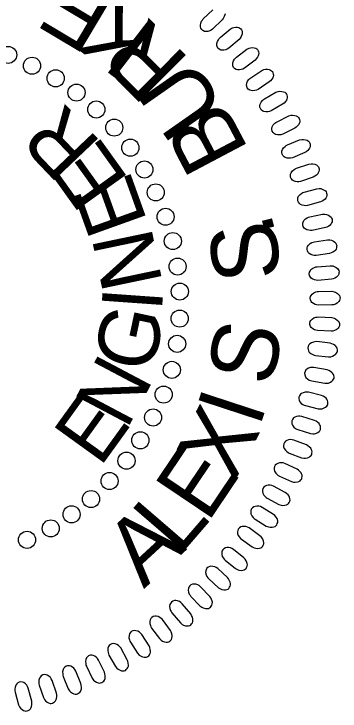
# Model space of a CAD drawing. Extents: x 477288 to 478604, y 497629 to 499448.
# Drawn here: x 477429.2 to 477459.8, y 499208.8 to 499274.1 of the extents above; entities that cross this region are included whole.
import ezdxf

# ---------------------------------------------------------------- set-up
doc = ezdxf.new("R2010")
doc.units = 0
doc.layers.add('Sheet PE Seal Cell', color=7, linetype='Continuous')

msp = doc.modelspace()

# ---------------------------------------------------------------- linework, layer by layer
at = {"layer": 'Sheet PE Seal Cell'}
msp.add_lwpolyline([(477449.002, 499274.089), (477448.987, 499273.991), (477448.925, 499273.838), (477448.838, 499273.671), (477448.739, 499273.544), (477447.839, 499272.667), (477447.7, 499272.566), (477447.568, 499272.502), (477447.392, 499272.456), (477447.213, 499272.439), (477447.088, 499272.454), (477446.936, 499272.526), (477446.818, 499272.62), (477446.743, 499272.756), (477446.707, 499272.865), (477446.69, 499273.026), (477446.729, 499273.229), (477446.812, 499273.403), (477446.885, 499273.514), (477446.968, 499273.615), (477447.852, 499274.465)], dxfattribs=at)
for points in [[(477448.552, 499271.872), (477449.487, 499272.666), (477449.679, 499272.779), (477449.819, 499272.83), (477450.021, 499272.854), (477450.168, 499272.851), (477450.301, 499272.817), (477450.399, 499272.764), (477450.487, 499272.69), (477450.544, 499272.592), (477450.599, 499272.481), (477450.621, 499272.363), (477450.612, 499272.219), (477450.59, 499272.121), (477450.52, 499271.973), (477450.421, 499271.811), (477450.315, 499271.691), (477449.361, 499270.873), (477449.217, 499270.78), (477449.082, 499270.724), (477448.902, 499270.689), (477448.723, 499270.684), (477448.599, 499270.707), (477448.452, 499270.788), (477448.34, 499270.89), (477448.273, 499271.029), (477448.244, 499271.141), (477448.237, 499271.302), (477448.29, 499271.503), (477448.383, 499271.671), (477448.463, 499271.777)], [(477450.074, 499270.046), (477451.058, 499270.779), (477451.256, 499270.88), (477451.399, 499270.922), (477451.602, 499270.934), (477451.748, 499270.921), (477451.879, 499270.879), (477451.974, 499270.819), (477452.057, 499270.74), (477452.107, 499270.639), (477452.155, 499270.525), (477452.17, 499270.406), (477452.152, 499270.262), (477452.124, 499270.166), (477452.044, 499270.023), (477451.936, 499269.868), (477451.822, 499269.754), (477450.819, 499268.998), (477450.669, 499268.914), (477450.53, 499268.867), (477450.349, 499268.843), (477450.17, 499268.849), (477450.048, 499268.88), (477449.906, 499268.97), (477449.8, 499269.078), (477449.744, 499269.221), (477449.721, 499269.336), (477449.724, 499269.497), (477449.789, 499269.694), (477449.893, 499269.856), (477449.979, 499269.956)], [(477451.417, 499268.111), (477452.445, 499268.781), (477452.649, 499268.869), (477452.794, 499268.902), (477452.998, 499268.901), (477453.143, 499268.879), (477453.271, 499268.828), (477453.361, 499268.763), (477453.44, 499268.679), (477453.483, 499268.575), (477453.524, 499268.458), (477453.532, 499268.338), (477453.504, 499268.196), (477453.471, 499268.102), (477453.382, 499267.964), (477453.264, 499267.816), (477453.143, 499267.71), (477452.094, 499267.018), (477451.94, 499266.944), (477451.798, 499266.905), (477451.616, 499266.893), (477451.438, 499266.911), (477451.318, 499266.949), (477451.182, 499267.047), (477451.083, 499267.162), (477451.036, 499267.309), (477451.02, 499267.424), (477451.034, 499267.584), (477451.111, 499267.777), (477451.225, 499267.932), (477451.317, 499268.028)], [(477452.708, 499266.142), (477453.776, 499266.746), (477453.985, 499266.821), (477454.132, 499266.845), (477454.335, 499266.831), (477454.478, 499266.8), (477454.603, 499266.742), (477454.689, 499266.671), (477454.762, 499266.583), (477454.799, 499266.475), (477454.832, 499266.357), (477454.832, 499266.236), (477454.797, 499266.096), (477454.757, 499266.004), (477454.66, 499265.872), (477454.533, 499265.732), (477454.405, 499265.634), (477453.315, 499265.009), (477453.156, 499264.945), (477453.013, 499264.915), (477452.83, 499264.914), (477452.653, 499264.943), (477452.536, 499264.989), (477452.406, 499265.095), (477452.315, 499265.216), (477452.276, 499265.365), (477452.269, 499265.482), (477452.293, 499265.641), (477452.381, 499265.828), (477452.504, 499265.976), (477452.602, 499266.065)], [(477453.875, 499263.99), (477454.978, 499264.526), (477455.191, 499264.588), (477455.34, 499264.602), (477455.542, 499264.576), (477455.683, 499264.536), (477455.804, 499264.47), (477455.885, 499264.393), (477455.952, 499264.3), (477455.983, 499264.191), (477456.008, 499264.071), (477456, 499263.951), (477455.956, 499263.813), (477455.911, 499263.724), (477455.805, 499263.598), (477455.67, 499263.466), (477455.536, 499263.376), (477454.409, 499262.82), (477454.247, 499262.767), (477454.102, 499262.746), (477453.92, 499262.757), (477453.745, 499262.797), (477453.63, 499262.85), (477453.508, 499262.965), (477453.425, 499263.09), (477453.396, 499263.242), (477453.395, 499263.358), (477453.428, 499263.516), (477453.529, 499263.697), (477453.661, 499263.837), (477453.764, 499263.92)], [(477454.855, 499261.812), (477455.991, 499262.278), (477456.207, 499262.327), (477456.357, 499262.332), (477456.556, 499262.292), (477456.695, 499262.244), (477456.811, 499262.17), (477456.888, 499262.089), (477456.948, 499261.992), (477456.972, 499261.882), (477456.99, 499261.759), (477456.975, 499261.64), (477456.922, 499261.505), (477456.871, 499261.42), (477456.758, 499261.3), (477456.615, 499261.177), (477456.475, 499261.096), (477455.316, 499260.612), (477455.15, 499260.568), (477455.005, 499260.557), (477454.822, 499260.579), (477454.651, 499260.63), (477454.54, 499260.69), (477454.425, 499260.812), (477454.35, 499260.943), (477454.331, 499261.096), (477454.337, 499261.212), (477454.38, 499261.368), (477454.492, 499261.542), (477454.633, 499261.673), (477454.741, 499261.75)], [(477455.703, 499259.623), (477456.866, 499260.016), (477457.085, 499260.051), (477457.234, 499260.047), (477457.431, 499259.995), (477457.566, 499259.937), (477457.678, 499259.857), (477457.749, 499259.771), (477457.803, 499259.67), (477457.82, 499259.558), (477457.83, 499259.436), (477457.808, 499259.317), (477457.746, 499259.186), (477457.69, 499259.104), (477457.57, 499258.992), (477457.419, 499258.878), (477457.275, 499258.805), (477456.087, 499258.395), (477455.92, 499258.362), (477455.773, 499258.36), (477455.593, 499258.394), (477455.425, 499258.455), (477455.318, 499258.522), (477455.211, 499258.651), (477455.145, 499258.787), (477455.135, 499258.941), (477455.148, 499259.056), (477455.201, 499259.208), (477455.324, 499259.376), (477455.473, 499259.498), (477455.585, 499259.567)], [(477456.429, 499257.386), (477457.614, 499257.706), (477457.835, 499257.727), (477457.983, 499257.714), (477458.177, 499257.649), (477458.308, 499257.584), (477458.414, 499257.496), (477458.479, 499257.406), (477458.528, 499257.302), (477458.538, 499257.189), (477458.541, 499257.066), (477458.51, 499256.95), (477458.441, 499256.822), (477458.379, 499256.744), (477458.252, 499256.639), (477458.095, 499256.535), (477457.947, 499256.472), (477456.735, 499256.137), (477456.566, 499256.115), (477456.419, 499256.122), (477456.242, 499256.167), (477456.078, 499256.238), (477455.975, 499256.312), (477455.877, 499256.448), (477455.819, 499256.587), (477455.819, 499256.742), (477455.84, 499256.856), (477455.902, 499257.004), (477456.035, 499257.163), (477456.191, 499257.276), (477456.308, 499257.338)], [(477456.947, 499255.07), (477458.15, 499255.314), (477458.372, 499255.322), (477458.519, 499255.299), (477458.708, 499255.222), (477458.835, 499255.15), (477458.935, 499255.055), (477458.995, 499254.961), (477459.037, 499254.855), (477459.039, 499254.741), (477459.034, 499254.618), (477458.996, 499254.503), (477458.919, 499254.381), (477458.853, 499254.306), (477458.72, 499254.211), (477458.556, 499254.116), (477458.404, 499254.063), (477457.174, 499253.804), (477457.004, 499253.792), (477456.858, 499253.809), (477456.684, 499253.865), (477456.524, 499253.947), (477456.427, 499254.026), (477456.337, 499254.168), (477456.288, 499254.311), (477456.297, 499254.465), (477456.325, 499254.577), (477456.397, 499254.722), (477456.54, 499254.873), (477456.702, 499254.975), (477456.823, 499255.03)], [(477457.394, 499252.743), (477458.61, 499252.911), (477458.832, 499252.904), (477458.978, 499252.872), (477459.161, 499252.784), (477459.283, 499252.703), (477459.378, 499252.602), (477459.432, 499252.505), (477459.466, 499252.396), (477459.462, 499252.283), (477459.449, 499252.16), (477459.405, 499252.048), (477459.32, 499251.93), (477459.249, 499251.86), (477459.11, 499251.773), (477458.941, 499251.689), (477458.786, 499251.645), (477457.542, 499251.465), (477457.371, 499251.464), (477457.227, 499251.489), (477457.056, 499251.556), (477456.903, 499251.647), (477456.81, 499251.733), (477456.729, 499251.88), (477456.689, 499252.026), (477456.708, 499252.179), (477456.743, 499252.29), (477456.823, 499252.43), (477456.975, 499252.571), (477457.144, 499252.663), (477457.269, 499252.709)], [(477457.648, 499250.402), (477458.871, 499250.494), (477459.092, 499250.473), (477459.236, 499250.432), (477459.414, 499250.332), (477459.531, 499250.244), (477459.618, 499250.138), (477459.666, 499250.037), (477459.694, 499249.925), (477459.682, 499249.813), (477459.662, 499249.692), (477459.61, 499249.583), (477459.518, 499249.471), (477459.443, 499249.405), (477459.299, 499249.327), (477459.125, 499249.253), (477458.967, 499249.219), (477457.715, 499249.117), (477457.544, 499249.127), (477457.401, 499249.162), (477457.236, 499249.239), (477457.088, 499249.34), (477457.001, 499249.431), (477456.93, 499249.583), (477456.899, 499249.731), (477456.927, 499249.883), (477456.969, 499249.991), (477457.059, 499250.125), (477457.219, 499250.257), (477457.393, 499250.338), (477457.52, 499250.377)], [(477457.772, 499248.079), (477458.998, 499248.094), (477459.218, 499248.06), (477459.359, 499248.009), (477459.53, 499247.899), (477459.64, 499247.803), (477459.722, 499247.692), (477459.763, 499247.588), (477459.784, 499247.476), (477459.765, 499247.364), (477459.737, 499247.244), (477459.679, 499247.138), (477459.58, 499247.033), (477459.501, 499246.972), (477459.352, 499246.903), (477459.173, 499246.841), (477459.014, 499246.816), (477457.758, 499246.793), (477457.588, 499246.814), (477457.448, 499246.857), (477457.287, 499246.945), (477457.146, 499247.055), (477457.065, 499247.151), (477457.003, 499247.307), (477456.982, 499247.457), (477457.02, 499247.607), (477457.068, 499247.712), (477457.166, 499247.841), (477457.334, 499247.961), (477457.513, 499248.031), (477457.643, 499248.063)], [(477457.775, 499245.691), (477459, 499245.629), (477459.217, 499245.581), (477459.354, 499245.521), (477459.518, 499245.401), (477459.622, 499245.298), (477459.696, 499245.182), (477459.731, 499245.076), (477459.745, 499244.962), (477459.72, 499244.852), (477459.684, 499244.734), (477459.619, 499244.632), (477459.514, 499244.533), (477459.431, 499244.477), (477459.278, 499244.417), (477459.096, 499244.367), (477458.935, 499244.352), (477457.68, 499244.409), (477457.512, 499244.44), (477457.375, 499244.492), (477457.22, 499244.589), (477457.086, 499244.708), (477457.011, 499244.809), (477456.96, 499244.968), (477456.947, 499245.12), (477456.995, 499245.266), (477457.05, 499245.369), (477457.155, 499245.491), (477457.331, 499245.601), (477457.514, 499245.66), (477457.644, 499245.682)], [(477457.48, 499242.094), (477458.699, 499241.955), (477458.92, 499241.968), (477459.066, 499242.003), (477459.247, 499242.096), (477459.367, 499242.18), (477459.459, 499242.283), (477459.511, 499242.382), (477459.543, 499242.491), (477459.535, 499242.604), (477459.519, 499242.727), (477459.472, 499242.837), (477459.385, 499242.953), (477459.313, 499243.021), (477459.171, 499243.105), (477458.999, 499243.185), (477458.843, 499243.225), (477457.596, 499243.375), (477457.425, 499243.371), (477457.281, 499243.342), (477457.112, 499243.271), (477456.961, 499243.176), (477456.871, 499243.088), (477456.793, 499242.939), (477456.757, 499242.793), (477456.78, 499242.639), (477456.818, 499242.53), (477456.902, 499242.392), (477457.057, 499242.255), (477457.228, 499242.167), (477457.353, 499242.124)], [(477457.135, 499239.691), (477458.343, 499239.476), (477458.566, 499239.474), (477458.712, 499239.501), (477458.899, 499239.581), (477459.024, 499239.658), (477459.122, 499239.755), (477459.179, 499239.85), (477459.219, 499239.957), (477459.219, 499240.071), (477459.21, 499240.194), (477459.17, 499240.308), (477459.089, 499240.428), (477459.022, 499240.501), (477458.886, 499240.594), (477458.72, 499240.684), (477458.567, 499240.734), (477457.331, 499240.962), (477457.16, 499240.969), (477457.015, 499240.949), (477456.842, 499240.889), (477456.685, 499240.804), (477456.589, 499240.721), (477456.503, 499240.578), (477456.457, 499240.434), (477456.47, 499240.279), (477456.502, 499240.168), (477456.577, 499240.025), (477456.723, 499239.878), (477456.888, 499239.78), (477457.01, 499239.728)], [(477456.546, 499237.379), (477457.738, 499237.088), (477457.96, 499237.072), (477458.108, 499237.09), (477458.3, 499237.159), (477458.429, 499237.227), (477458.533, 499237.318), (477458.597, 499237.41), (477458.643, 499237.514), (477458.65, 499237.627), (477458.649, 499237.751), (477458.616, 499237.867), (477458.543, 499237.992), (477458.48, 499238.069), (477458.351, 499238.17), (477458.191, 499238.27), (477458.041, 499238.33), (477456.822, 499238.635), (477456.652, 499238.653), (477456.506, 499238.642), (477456.329, 499238.593), (477456.167, 499238.518), (477456.066, 499238.442), (477455.971, 499238.304), (477455.916, 499238.162), (477455.92, 499238.008), (477455.944, 499237.895), (477456.01, 499237.748), (477456.147, 499237.591), (477456.306, 499237.483), (477456.424, 499237.424)], [(477455.841, 499235.132), (477457.012, 499234.768), (477457.232, 499234.739), (477457.381, 499234.747), (477457.577, 499234.803), (477457.711, 499234.863), (477457.82, 499234.947), (477457.889, 499235.034), (477457.941, 499235.136), (477457.955, 499235.249), (477457.963, 499235.372), (477457.937, 499235.49), (477457.872, 499235.62), (477457.814, 499235.701), (477457.691, 499235.809), (477457.538, 499235.92), (477457.392, 499235.989), (477456.195, 499236.369), (477456.025, 499236.398), (477455.879, 499236.396), (477455.7, 499236.359), (477455.533, 499236.293), (477455.428, 499236.224), (477455.325, 499236.092), (477455.261, 499235.954), (477455.255, 499235.801), (477455.271, 499235.685), (477455.328, 499235.535), (477455.455, 499235.371), (477455.607, 499235.252), (477455.721, 499235.186)], [(477455.029, 499232.94), (477456.175, 499232.503), (477456.393, 499232.46), (477456.542, 499232.458), (477456.741, 499232.503), (477456.878, 499232.554), (477456.992, 499232.631), (477457.067, 499232.714), (477457.126, 499232.812), (477457.147, 499232.923), (477457.162, 499233.046), (477457.144, 499233.165), (477457.087, 499233.298), (477457.034, 499233.382), (477456.918, 499233.499), (477456.772, 499233.619), (477456.631, 499233.697), (477455.459, 499234.152), (477455.293, 499234.191), (477455.146, 499234.199), (477454.966, 499234.172), (477454.795, 499234.118), (477454.686, 499234.055), (477454.574, 499233.93), (477454.502, 499233.797), (477454.486, 499233.644), (477454.495, 499233.528), (477454.543, 499233.373), (477454.659, 499233.202), (477454.803, 499233.074), (477454.913, 499233)], [(477454.103, 499230.774), (477455.22, 499230.266), (477455.435, 499230.208), (477455.583, 499230.198), (477455.784, 499230.229), (477455.924, 499230.273), (477456.043, 499230.342), (477456.123, 499230.42), (477456.187, 499230.514), (477456.216, 499230.624), (477456.239, 499230.746), (477456.227, 499230.866), (477456.18, 499231.002), (477456.132, 499231.09), (477456.024, 499231.213), (477455.886, 499231.342), (477455.749, 499231.429), (477454.609, 499231.956), (477454.445, 499232.006), (477454.3, 499232.023), (477454.117, 499232.008), (477453.944, 499231.964), (477453.831, 499231.908), (477453.711, 499231.79), (477453.631, 499231.662), (477453.606, 499231.509), (477453.608, 499231.394), (477453.645, 499231.237), (477453.75, 499231.058), (477453.886, 499230.922), (477453.991, 499230.841)], [(477452.965, 499228.695), (477454.048, 499228.118), (477454.259, 499228.048), (477454.407, 499228.028), (477454.609, 499228.047), (477454.752, 499228.081), (477454.875, 499228.143), (477454.959, 499228.216), (477455.03, 499228.306), (477455.065, 499228.414), (477455.095, 499228.534), (477455.092, 499228.654), (477455.052, 499228.793), (477455.011, 499228.884), (477454.91, 499229.013), (477454.78, 499229.15), (477454.65, 499229.246), (477453.545, 499229.844), (477453.385, 499229.904), (477453.24, 499229.93), (477453.058, 499229.926), (477452.881, 499229.894), (477452.765, 499229.845), (477452.638, 499229.735), (477452.55, 499229.612), (477452.515, 499229.461), (477452.51, 499229.345), (477452.538, 499229.187), (477452.632, 499229.002), (477452.758, 499228.857), (477452.859, 499228.77)], [(477451.824, 499226.739), (477452.868, 499226.094), (477453.074, 499226.011), (477453.22, 499225.981), (477453.423, 499225.988), (477453.568, 499226.013), (477453.695, 499226.066), (477453.784, 499226.134), (477453.86, 499226.22), (477453.901, 499226.325), (477453.938, 499226.443), (477453.943, 499226.563), (477453.912, 499226.705), (477453.877, 499226.798), (477453.785, 499226.933), (477453.663, 499227.079), (477453.539, 499227.182), (477452.474, 499227.848), (477452.318, 499227.918), (477452.175, 499227.953), (477451.993, 499227.961), (477451.815, 499227.939), (477451.695, 499227.898), (477451.563, 499227.796), (477451.467, 499227.679), (477451.423, 499227.531), (477451.41, 499227.415), (477451.428, 499227.255), (477451.51, 499227.065), (477451.627, 499226.912), (477451.721, 499226.819)], [(477450.541, 499224.854), (477451.542, 499224.145), (477451.743, 499224.049), (477451.887, 499224.011), (477452.09, 499224.004), (477452.237, 499224.02), (477452.366, 499224.066), (477452.458, 499224.128), (477452.54, 499224.208), (477452.588, 499224.311), (477452.633, 499224.426), (477452.645, 499224.546), (477452.623, 499224.689), (477452.593, 499224.783), (477452.51, 499224.926), (477452.398, 499225.078), (477452.281, 499225.189), (477451.259, 499225.92), (477451.108, 499226), (477450.968, 499226.044), (477450.786, 499226.063), (477450.608, 499226.052), (477450.487, 499226.019), (477450.347, 499225.926), (477450.244, 499225.815), (477450.19, 499225.67), (477450.171, 499225.555), (477450.178, 499225.394), (477450.248, 499225.199), (477450.356, 499225.04), (477450.444, 499224.941)], [(477449.019, 499222.89), (477449.974, 499222.12), (477450.167, 499222.011), (477450.309, 499221.964), (477450.512, 499221.944), (477450.658, 499221.952), (477450.791, 499221.989), (477450.888, 499222.045), (477450.973, 499222.12), (477451.028, 499222.22), (477451.08, 499222.332), (477451.099, 499222.45), (477451.087, 499222.595), (477451.063, 499222.691), (477450.989, 499222.838), (477450.886, 499222.997), (477450.777, 499223.115), (477449.803, 499223.909), (477449.657, 499223.999), (477449.52, 499224.051), (477449.34, 499224.082), (477449.161, 499224.082), (477449.038, 499224.056), (477448.892, 499223.972), (477448.783, 499223.868), (477448.72, 499223.727), (477448.693, 499223.613), (477448.691, 499223.452), (477448.748, 499223.253), (477448.846, 499223.087), (477448.928, 499222.983)], [(477447.474, 499221.15), (477448.378, 499220.321), (477448.565, 499220.201), (477448.703, 499220.145), (477448.904, 499220.113), (477449.05, 499220.11), (477449.185, 499220.139), (477449.285, 499220.189), (477449.376, 499220.259), (477449.436, 499220.355), (477449.495, 499220.464), (477449.522, 499220.581), (477449.519, 499220.725), (477449.501, 499220.823), (477449.436, 499220.975), (477449.344, 499221.139), (477449.242, 499221.264), (477448.32, 499222.119), (477448.18, 499222.216), (477448.046, 499222.277), (477447.868, 499222.319), (477447.689, 499222.331), (477447.565, 499222.313), (477447.415, 499222.238), (477447.299, 499222.141), (477447.228, 499222.004), (477447.194, 499221.893), (477447.181, 499221.732), (477447.225, 499221.529), (477447.312, 499221.358), (477447.388, 499221.249)], [(477445.803, 499219.501), (477446.655, 499218.617), (477446.833, 499218.485), (477446.968, 499218.42), (477447.166, 499218.376), (477447.312, 499218.364), (477447.448, 499218.385), (477447.551, 499218.428), (477447.647, 499218.492), (477447.713, 499218.584), (477447.778, 499218.688), (477447.813, 499218.804), (477447.818, 499218.948), (477447.806, 499219.048), (477447.751, 499219.202), (477447.67, 499219.373), (477447.576, 499219.503), (477446.709, 499220.413), (477446.575, 499220.52), (477446.446, 499220.59), (477446.271, 499220.643), (477446.094, 499220.665), (477445.968, 499220.656), (477445.813, 499220.59), (477445.692, 499220.5), (477445.612, 499220.368), (477445.571, 499220.26), (477445.548, 499220.099), (477445.58, 499219.895), (477445.656, 499219.718), (477445.724, 499219.604)], [(477444.023, 499217.965), (477444.817, 499217.029), (477444.987, 499216.885), (477445.117, 499216.813), (477445.313, 499216.756), (477445.457, 499216.735), (477445.595, 499216.747), (477445.7, 499216.784), (477445.799, 499216.842), (477445.871, 499216.93), (477445.943, 499217.03), (477445.984, 499217.143), (477446, 499217.287), (477445.994, 499217.386), (477445.948, 499217.544), (477445.877, 499217.719), (477445.792, 499217.855), (477444.985, 499218.819), (477444.858, 499218.933), (477444.732, 499219.011), (477444.562, 499219.074), (477444.386, 499219.109), (477444.26, 499219.106), (477444.101, 499219.05), (477443.975, 499218.969), (477443.886, 499218.842), (477443.839, 499218.736), (477443.806, 499218.578), (477443.825, 499218.371), (477443.89, 499218.19), (477443.951, 499218.073)], [(477442.128, 499216.533), (477442.861, 499215.549), (477443.022, 499215.396), (477443.147, 499215.315), (477443.338, 499215.246), (477443.483, 499215.216), (477443.62, 499215.22), (477443.727, 499215.25), (477443.829, 499215.301), (477443.907, 499215.384), (477443.985, 499215.48), (477444.033, 499215.59), (477444.057, 499215.733), (477444.058, 499215.832), (477444.022, 499215.992), (477443.963, 499216.172), (477443.886, 499216.314), (477443.141, 499217.326), (477443.021, 499217.448), (477442.901, 499217.533), (477442.735, 499217.607), (477442.562, 499217.652), (477442.436, 499217.658), (477442.274, 499217.612), (477442.142, 499217.538), (477442.046, 499217.417), (477441.992, 499217.315), (477441.95, 499217.159), (477441.956, 499216.952), (477442.009, 499216.767), (477442.062, 499216.646)], [(477440.144, 499215.2), (477440.814, 499214.172), (477440.965, 499214.009), (477441.085, 499213.92), (477441.272, 499213.84), (477441.413, 499213.8), (477441.551, 499213.795), (477441.66, 499213.819), (477441.765, 499213.863), (477441.848, 499213.941), (477441.932, 499214.032), (477441.987, 499214.139), (477442.019, 499214.28), (477442.027, 499214.379), (477442.001, 499214.541), (477441.953, 499214.724), (477441.885, 499214.87), (477441.205, 499215.927), (477441.093, 499216.057), (477440.98, 499216.149), (477440.818, 499216.233), (477440.647, 499216.29), (477440.522, 499216.303), (477440.358, 499216.268), (477440.221, 499216.203), (477440.118, 499216.088), (477440.058, 499215.988), (477440.005, 499215.836), (477439.999, 499215.629), (477440.04, 499215.441), (477440.086, 499215.316)], [(477438.129, 499214.011), (477438.733, 499212.943), (477438.874, 499212.77), (477438.988, 499212.674), (477439.169, 499212.582), (477439.308, 499212.535), (477439.445, 499212.521), (477439.555, 499212.537), (477439.663, 499212.575), (477439.75, 499212.647), (477439.84, 499212.733), (477439.902, 499212.836), (477439.943, 499212.975), (477439.956, 499213.073), (477439.941, 499213.237), (477439.904, 499213.422), (477439.846, 499213.572), (477439.234, 499214.67), (477439.13, 499214.807), (477439.022, 499214.906), (477438.866, 499215), (477438.7, 499215.067), (477438.576, 499215.088), (477438.409, 499215.063), (477438.269, 499215.007), (477438.16, 499214.899), (477438.093, 499214.803), (477438.031, 499214.654), (477438.011, 499214.448), (477438.04, 499214.258), (477438.079, 499214.131)], [(477436.018, 499212.951), (477436.554, 499211.848), (477436.683, 499211.667), (477436.791, 499211.563), (477436.966, 499211.46), (477437.102, 499211.404), (477437.237, 499211.381), (477437.349, 499211.391), (477437.458, 499211.422), (477437.55, 499211.489), (477437.645, 499211.568), (477437.713, 499211.667), (477437.763, 499211.803), (477437.783, 499211.901), (477437.778, 499212.065), (477437.753, 499212.253), (477437.704, 499212.406), (477437.161, 499213.54), (477437.067, 499213.682), (477436.965, 499213.788), (477436.815, 499213.892), (477436.654, 499213.969), (477436.531, 499213.999), (477436.364, 499213.983), (477436.22, 499213.936), (477436.104, 499213.835), (477436.031, 499213.745), (477435.961, 499213.6), (477435.927, 499213.395), (477435.945, 499213.204), (477435.975, 499213.074)], [(477433.846, 499211.989), (477434.311, 499210.853), (477434.43, 499210.665), (477434.53, 499210.555), (477434.699, 499210.441), (477434.83, 499210.376), (477434.965, 499210.345), (477435.076, 499210.348), (477435.188, 499210.372), (477435.283, 499210.433), (477435.383, 499210.506), (477435.457, 499210.601), (477435.516, 499210.734), (477435.541, 499210.83), (477435.547, 499210.994), (477435.534, 499211.183), (477435.494, 499211.339), (477435.024, 499212.504), (477434.939, 499212.653), (477434.844, 499212.764), (477434.701, 499212.878), (477434.544, 499212.965), (477434.425, 499213.002), (477434.256, 499212.998), (477434.11, 499212.959), (477433.987, 499212.866), (477433.909, 499212.779), (477433.829, 499212.639), (477433.783, 499212.437), (477433.789, 499212.245), (477433.811, 499212.114)], [(477431.593, 499211.191), (477431.987, 499210.029), (477432.092, 499209.833), (477432.186, 499209.718), (477432.348, 499209.593), (477432.475, 499209.52), (477432.606, 499209.481), (477432.718, 499209.476), (477432.831, 499209.493), (477432.93, 499209.548), (477433.034, 499209.615), (477433.114, 499209.705), (477433.181, 499209.833), (477433.212, 499209.928), (477433.228, 499210.092), (477433.227, 499210.281), (477433.198, 499210.439), (477432.801, 499211.631), (477432.726, 499211.785), (477432.638, 499211.903), (477432.503, 499212.025), (477432.351, 499212.122), (477432.234, 499212.166), (477432.066, 499212.172), (477431.918, 499212.143), (477431.789, 499212.057), (477431.706, 499211.977), (477431.618, 499211.841), (477431.559, 499211.643), (477431.553, 499211.45), (477431.566, 499211.319)], [(477429.336, 499210.54), (477429.655, 499209.356), (477429.749, 499209.154), (477429.835, 499209.032), (477429.988, 499208.898), (477430.111, 499208.817), (477430.24, 499208.77), (477430.351, 499208.759), (477430.465, 499208.768), (477430.567, 499208.817), (477430.675, 499208.877), (477430.761, 499208.962), (477430.836, 499209.086), (477430.873, 499209.179), (477430.899, 499209.34), (477430.91, 499209.529), (477430.89, 499209.689), (477430.57, 499210.904), (477430.504, 499211.062), (477430.424, 499211.185), (477430.296, 499211.316), (477430.152, 499211.421), (477430.037, 499211.473), (477429.87, 499211.49), (477429.72, 499211.47), (477429.586, 499211.393), (477429.498, 499211.317), (477429.401, 499211.188), (477429.33, 499210.993), (477429.312, 499210.802), (477429.317, 499210.669)]]:
    msp.add_lwpolyline(points, close=True, dxfattribs=at)
for centre in [(477428.685, 499270.25), (477430.918, 499269.233), (477433.133, 499268.054), (477435.088, 499266.717), (477436.94, 499265.129), (477438.624, 499263.433), (477440.132, 499261.552), (477441.448, 499259.507), (477442.51, 499257.364), (477443.431, 499255.08), (477444.109, 499252.802), (477444.561, 499250.413), (477444.766, 499248.07), (477444.756, 499245.536), (477444.521, 499243.173), (477444.015, 499240.731), (477443.251, 499238.414), (477442.262, 499236.267), (477441.07, 499234.132), (477439.767, 499232.222), (477438.182, 499230.314), (477436.445, 499228.626), (477434.622, 499227.192), (477432.673, 499225.876), (477430.449, 499224.804)]:
    msp.add_circle(centre, 0.801, dxfattribs=at)

# ---------------------------------------------------------------- texts
for s, height, rotation, p in [('E', 6.236, 149.19094, (477439.189, 499275.546)), ('K', 6.236, 142.34528, (477443, 499272.638)), ('R', 6.236, 135.07025, (477445.815, 499269.767)), ('U', 6.236, 124.97041, (477449.133, 499265.277)), ('R', 5.669, 133.58624, (477437.52, 499261.956)), ('B', 6.236, 117.85357, (477451.281, 499261.316)), ('E', 5.669, 125.64644, (477440.084, 499258.496)), ('E', 5.669, 109.76685, (477441.757, 499254.619)), ('.', 6.236, 104.15095, (477453.789, 499253.425)), ('S', 6.236, 97.30529, (477454.297, 499249.417)), ('N', 5.669, 101.82705, (477443.164, 499248.911)), ('I', 5.669, 85.94746, (477443.075, 499246.118)), ('G', 5.669, 78.00766, (477442.178, 499240.311)), ('S', 6.236, 78.7101, (477453.392, 499239.073)), ('N', 5.669, 62.12806, (477439.783, 499235.036)), ('E', 5.669, 54.18827, (477437.288, 499231.524)), ('I', 6.236, 71.86444, (477452.218, 499235.219)), ('X', 6.236, 62.91712, (477449.841, 499230.093)), ('E', 6.236, 56.07146, (477447.366, 499226.314)), ('L', 6.236, 49.2258, (477444.688, 499223.202)), ('A', 6.236, 42.60613, (477441.393, 499220.179))]:
    msp.add_text(s, height=height, rotation=rotation, dxfattribs=at).set_placement(p)

doc.saveas('drawing.dxf')
